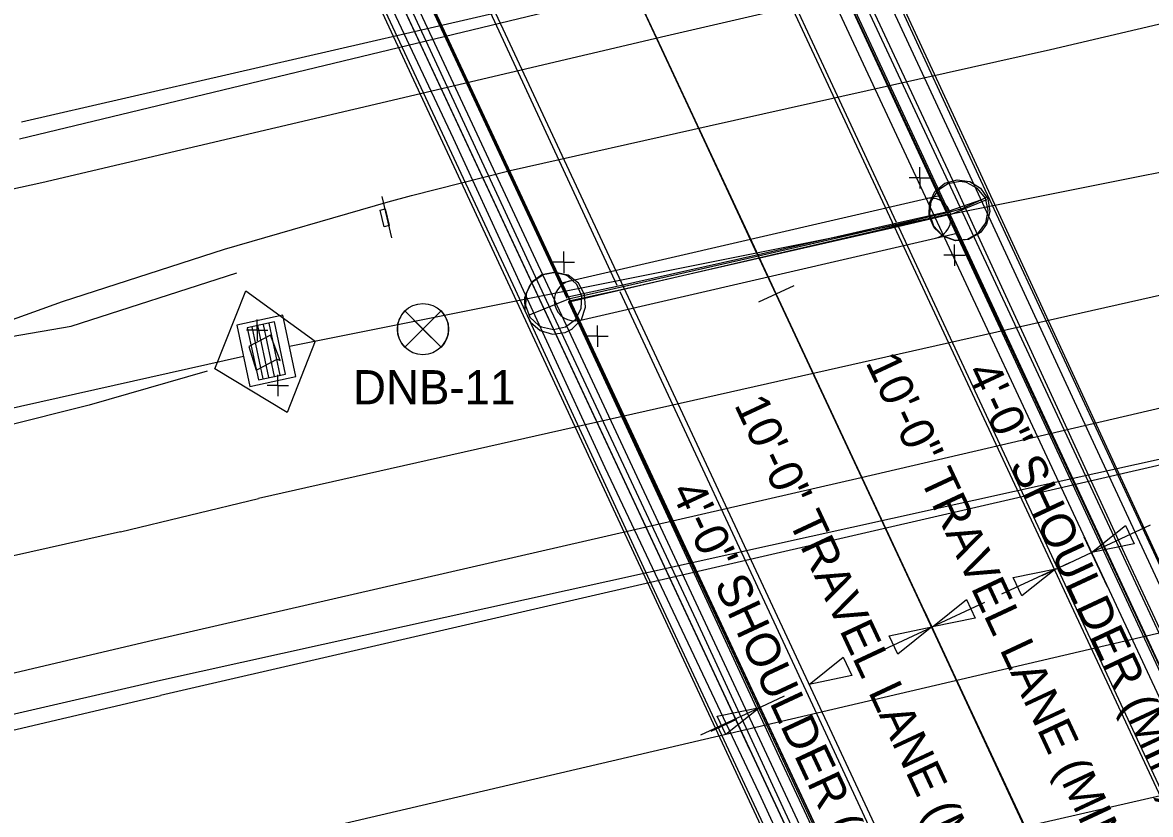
# Model space of a CAD drawing. Extents: x 1040567 to 1041254, y 1126791 to 1127594.
# Drawn here: x 1040909 to 1040992.3, y 1127132.4 to 1127190.9 of the extents above; entities that cross this region are included whole.
import ezdxf

# ---------------------------------------------------------------- set-up
doc = ezdxf.new("R2010")
doc.units = 0
for name, color, linetype in [('AC_P', 7, 'Continuous'), ('ACSRT_P', 7, 'Continuous'), ('BAJ', 7, 'Continuous'), ('BBR', 7, 'Continuous'), ('BCLBRG_P', 7, 'Continuous'), ('BDE', 7, 'Continuous'), ('BDE_P', 7, 'Continuous'), ('BDET_P', 7, 'Continuous'), ('BDSW', 7, 'Continuous'), ('BFNC', 7, 'Continuous'), ('BR', 7, 'Continuous'), ('BSE', 7, 'Continuous'), ('BSUBM', 7, 'Continuous'), ('BWI', 7, 'Continuous'), ('DCP', 7, 'Continuous'), ('DINV', 7, 'Continuous'), ('DS', 7, 'Continuous'), ('GDH', 7, 'Continuous'), ('GDH_C', 7, 'Continuous'), ('LELB', 7, 'Continuous'), ('LUKL', 7, 'Continuous'), ('O_Details_Dimensions_Extension_Lines_P', 7, 'Continuous'), ('PE', 7, 'Continuous'), ('PE_P', 7, 'Continuous'), ('PET', 7, 'Continuous'), ('PET_P', 7, 'Continuous'), ('PSU', 7, 'Continuous'), ('RBS_P', 7, 'Continuous'), ('RELB', 7, 'Continuous'), ('RGCB_P', 7, 'Continuous'), ('RGWM', 7, 'Continuous'), ('SDEL', 7, 'Continuous'), ('STBW', 7, 'Continuous'), ('STFBY', 7, 'Continuous'), ('STFBY_P', 7, 'Continuous'), ('STSEW', 7, 'Continuous'), ('STSEY', 7, 'Continuous')]:
    doc.layers.add(name, color=color, linetype=linetype)

msp = doc.modelspace()

# ---------------------------------------------------------------- linework, layer by layer
at = {"layer": 'AC_P'}
msp.add_line((1040885.873, 1127339.474), (1041008.875, 1127076.161), dxfattribs=at)
at = {"layer": 'ACSRT_P'}
msp.add_lwpolyline([(1040965.962, 1127171.427), (1040963.353, 1127170.208)], dxfattribs=at)
at = {"layer": 'BAJ'}
for points in [[(1040977.201, 1127176.865), (1040973.576, 1127176.055), (1040963.319, 1127173.7), (1040953.012, 1127171.4), (1040949.268, 1127170.586)], [(1040977.294, 1127176.639), (1040973.722, 1127175.799)], [(1040973.722, 1127175.799), (1040963.442, 1127173.467), (1040953.121, 1127171.099), (1040949.358, 1127170.29)]]:
    msp.add_lwpolyline(points, dxfattribs=at)
at = {"layer": 'BBR'}
for points in [[(1041019.719, 1127088.654), (1041004.406, 1127121.53), (1041003.585, 1127123.404), (1040990.693, 1127150.999), (1040979.268, 1127175.742), (1040977.886, 1127178.782), (1040965.491, 1127205.307), (1040953.611, 1127231.003), (1040952.138, 1127234.156), (1040937.531, 1127265.417)], [(1040989.084, 1127081.358), (1040979.685, 1127101.678), (1040973.812, 1127114.274), (1040972.939, 1127116.09), (1040958.781, 1127146.714), (1040948.043, 1127169.603), (1040947.215, 1127171.406), (1040934.066, 1127199.748), (1040923.012, 1127223.473), (1040921.387, 1127226.985), (1040913.364, 1127244.169), (1040907.222, 1127257.388)]]:
    msp.add_lwpolyline(points, dxfattribs=at)
at = {"layer": 'BCLBRG_P'}
msp.add_line((1040977.358, 1127176.709), (1040949.47, 1127170.251), dxfattribs=at)
at = {"layer": 'BDE'}
for points in [[(1040939.415, 1127265.922), (1040947.859, 1127247.808), (1040955.236, 1127232.05), (1040963.843, 1127213.367), (1040970.466, 1127199.289), (1040979.576, 1127179.6), (1040988.925, 1127159.501), (1040997.881, 1127140.234), (1041005.324, 1127124.249), (1041014.183, 1127105.141), (1041021.331, 1127089.904)], [(1040905.131, 1127257.422), (1040913.466, 1127239.609), (1040920.648, 1127224.278), (1040933.375, 1127196.889), (1040945.375, 1127171.145), (1040955.293, 1127149.679), (1040963.856, 1127131.323), (1040972.311, 1127113.367), (1040978.963, 1127098.619), (1040987.061, 1127081.333)]]:
    msp.add_lwpolyline(points, dxfattribs=at)
at = {"layer": 'BDE_P'}
msp.add_line((1040912.39, 1127244.904), (1040982.54, 1127094.731), dxfattribs=at)
at = {"layer": 'BDET_P'}
for p, q in [((1040941.284, 1127251.57), (1041011.459, 1127101.345)), ((1040914.383, 1127245.364), (1040984.534, 1127095.188))]:
    msp.add_line(p, q, dxfattribs=at)
at = {"layer": 'BDSW'}
for points in [[(1040938.228, 1127265.419), (1040936.751, 1127268.274), (1040935.099, 1127267.531), (1040944.282, 1127248.014), (1040951.626, 1127232.223), (1040953.838, 1127232.99), (1040954.435, 1127233.274), (1040954.508, 1127233.062), (1040952.645, 1127232.223), (1040951.738, 1127231.963), (1040962.689, 1127208.469), (1040977.373, 1127176.939), (1040979.827, 1127177.801), (1040980.125, 1127177.936)], [(1040951.593, 1127231.935), (1040962.526, 1127208.475), (1040977.201, 1127176.865)], [(1040923.626, 1127225.384), (1040937.857, 1127194.844), (1040949.201, 1127170.502)], [(1040949.268, 1127170.586), (1040934.086, 1127203.088), (1040923.736, 1127225.397)], [(1040980.191, 1127177.762), (1040977.506, 1127176.66), (1040987.541, 1127155.057), (1041003.054, 1127121.68), (1041005.386, 1127122.596), (1041005.717, 1127122.762)], [(1040977.294, 1127176.639), (1040987.324, 1127155.089), (1041002.898, 1127121.632)], [(1040949.328, 1127170.24), (1040964.707, 1127136.99), (1040974.918, 1127115.201)], [(1040975.07, 1127115.203), (1040960.723, 1127145.945), (1040949.358, 1127170.29)]]:
    msp.add_lwpolyline(points, dxfattribs=at)
at = {"layer": 'BFNC'}
for points in [[(1041029.028, 1127072.099), (1041018.346, 1127094.834), (1041008.209, 1127116.584), (1040997.724, 1127139.118), (1040988.217, 1127159.54), (1040977.754, 1127182.181), (1040967.557, 1127204.106), (1040957.206, 1127226.328), (1040946.955, 1127248.298), (1040937.324, 1127268.899), (1040930.675, 1127283.065)], [(1040995.864, 1127064.064), (1040985.169, 1127086.964), (1040974.401, 1127110.108), (1040963.406, 1127133.965), (1040952.032, 1127157.995), (1040940.832, 1127182.3), (1040930.319, 1127204.627), (1040919.348, 1127228.3), (1040907.363, 1127253.93), (1040897.309, 1127275.145)]]:
    msp.add_lwpolyline(points, dxfattribs=at)
at = {"layer": 'BR'}
for points in [[(1040938.828, 1127267.695), (1040955.714, 1127231.414), (1040967.747, 1127205.578), (1040979.747, 1127179.699), (1040993.173, 1127150.575), (1041022.323, 1127088.276)], [(1040904.042, 1127259.025), (1040921.201, 1127222.4), (1040933.244, 1127196.591), (1040950.275, 1127159.967), (1040963.843, 1127130.88), (1040975.411, 1127105.881), (1040987.575, 1127079.658)]]:
    msp.add_lwpolyline(points, dxfattribs=at)
at = {"layer": 'BSE'}
for p, q in [((1040948.817, 1127171.65), (1040976.713, 1127178.089)), ((1040950.115, 1127168.87), (1040978.011, 1127175.31))]:
    msp.add_line(p, q, dxfattribs=at)
for points in [[(1040978.238, 1127179.117), (1040977.325, 1127178.961), (1040976.56, 1127178.438), (1040976.082, 1127177.645), (1040975.979, 1127176.724), (1040976.269, 1127175.844), (1040976.9, 1127175.165), (1040976.981, 1127175.112), (1040977.852, 1127174.796), (1040978.775, 1127174.873), (1040979.582, 1127175.327), (1040980.127, 1127176.077), (1040980.309, 1127176.985), (1040980.096, 1127177.887), (1040979.526, 1127178.618), (1040978.704, 1127179.044), (1040978.238, 1127179.117)], [(1040949.137, 1127172.202), (1040948.249, 1127172.411), (1040947.355, 1127172.226), (1040946.623, 1127171.68), (1040946.19, 1127170.875), (1040946.138, 1127169.964), (1040946.476, 1127169.116), (1040947.141, 1127168.49), (1040947.329, 1127168.39)], [(1040947.329, 1127168.39), (1040948.22, 1127168.193), (1040949.112, 1127168.39), (1040949.836, 1127168.946), (1040950.258, 1127169.756), (1040950.298, 1127170.668), (1040949.949, 1127171.512), (1040949.276, 1127172.129), (1040949.137, 1127172.202)]]:
    msp.add_lwpolyline(points, dxfattribs=at)
for centre, start, end in [((1040976.054, 1127176.398), 282.99926, 102.99926), ((1040949.776, 1127170.336), 102.99926, 282.99926)]:
    msp.add_arc(centre, 1.5, start, end, dxfattribs=at)
at = {"layer": 'BSUBM'}
for points in [[(1040976.376, 1127178.375), (1040977.097, 1127178.988), (1040978.005, 1127179.252), (1040978.941, 1127179.121), (1040979.743, 1127178.619), (1040980.269, 1127177.833), (1040980.427, 1127176.901), (1040980.19, 1127175.985), (1040979.759, 1127175.39), (1040979.759, 1127175.39), (1040979.664, 1127175.302), (1040978.84, 1127174.838), (1040977.899, 1127174.752), (1040977.004, 1127175.059), (1040976.313, 1127175.705), (1040975.947, 1127176.576), (1040975.969, 1127177.522), (1040976.376, 1127178.375)], [(1040949.628, 1127168.261), (1040950.272, 1127168.941), (1040950.588, 1127169.837), (1040950.512, 1127170.785), (1040950.056, 1127171.62), (1040949.301, 1127172.197), (1040948.375, 1127172.417), (1040947.441, 1127172.241), (1040946.659, 1127171.7), (1040946.438, 1127171.426), (1040946.074, 1127170.547), (1040946.1, 1127169.597), (1040946.51, 1127168.739), (1040947.234, 1127168.122), (1040948.146, 1127167.854), (1040949.089, 1127167.98), (1040949.618, 1127168.25)], [(1040949.618, 1127168.25), (1040949.628, 1127168.261)]]:
    msp.add_lwpolyline(points, dxfattribs=at)
at = {"layer": 'BWI'}
for p, q in [((1040975.261, 1127179.39), (1040974.473, 1127179.39)), ((1040975.261, 1127179.39), (1040975.261, 1127180.177)), ((1040975.261, 1127179.39), (1040976.048, 1127179.39)), ((1040975.261, 1127179.39), (1040975.261, 1127178.603)), ((1040977.816, 1127173.688), (1040977.816, 1127174.476)), ((1040948.977, 1127173.175), (1040948.977, 1127173.963)), ((1040977.816, 1127173.688), (1040977.028, 1127173.688)), ((1040977.816, 1127173.688), (1040978.603, 1127173.688)), ((1040977.816, 1127173.688), (1040977.816, 1127172.901)), ((1040948.977, 1127173.175), (1040948.189, 1127173.175)), ((1040948.977, 1127173.175), (1040949.764, 1127173.175)), ((1040948.977, 1127173.175), (1040948.977, 1127172.388)), ((1040951.452, 1127167.71), (1040951.452, 1127168.498)), ((1040951.452, 1127167.71), (1040950.665, 1127167.71)), ((1040951.452, 1127167.71), (1040952.24, 1127167.71)), ((1040951.452, 1127167.71), (1040951.452, 1127166.923))]:
    msp.add_line(p, q, dxfattribs=at)
at = {"layer": 'DCP'}
for points in [[(1040928.726, 1127166.959), (1041013.434, 1127183.902)], [(1040825.333, 1127143.822), (1040925.323, 1127166.237)]]:
    msp.add_lwpolyline(points, dxfattribs=at)
at = {"layer": 'DINV'}
for p, q in [((1040926.334, 1127168.151), (1040926.334, 1127168.939)), ((1040926.334, 1127168.151), (1040925.547, 1127168.151)), ((1040926.334, 1127168.151), (1040927.121, 1127168.151)), ((1040926.334, 1127168.151), (1040926.334, 1127167.364)), ((1040927.859, 1127164.069), (1040927.859, 1127164.857)), ((1040927.859, 1127164.069), (1040927.072, 1127164.069)), ((1040927.859, 1127164.069), (1040928.647, 1127164.069)), ((1040927.859, 1127164.069), (1040927.859, 1127163.282))]:
    msp.add_line(p, q, dxfattribs=at)
at = {"layer": 'DS'}
for p, q in [((1040926.777, 1127168.575), (1040927.598, 1127164.732)), ((1040927.194, 1127168.664), (1040928.015, 1127164.821)), ((1040925.942, 1127168.397), (1040926.763, 1127164.553)), ((1040926.36, 1127168.486), (1040927.181, 1127164.642))]:
    msp.add_line(p, q, dxfattribs=at)
for points in [[(1040924.836, 1127168.518), (1040925.803, 1127163.99), (1040929.204, 1127164.717), (1040928.237, 1127169.245)], [(1040925.609, 1127168.325), (1040926.43, 1127164.482), (1040928.432, 1127164.91), (1040927.611, 1127168.753)]]:
    msp.add_lwpolyline(points, close=True, dxfattribs=at)
at = {"layer": 'GDH'}
for p, q in [((1040937.244, 1127169.564), (1040939.917, 1127166.891)), ((1040939.917, 1127169.564), (1040937.244, 1127166.891))]:
    msp.add_line(p, q, dxfattribs=at)
for points in [[(1040937.244, 1127166.891), (1040938.58, 1127168.228), (1040937.244, 1127169.564)], [(1040939.917, 1127169.564), (1040938.58, 1127168.228), (1040939.917, 1127166.891)]]:
    msp.add_lwpolyline(points, dxfattribs=at)
msp.add_circle((1040938.58, 1127168.228), 1.89, dxfattribs=at)
for start, end in [(135, 180), (360, 45), (180, 225), (315, 0)]:
    msp.add_arc((1040938.58, 1127168.228), 1.89, start, end, dxfattribs=at)
at = {"layer": 'LELB'}
msp.add_lwpolyline([(1040925.719, 1127166.953), (1040926.265, 1127165.193), (1040927.812, 1127165.998), (1040928.04, 1127165.914), (1040927.331, 1127167.785), (1040925.719, 1127166.953)], dxfattribs=at)
at = {"layer": 'LUKL'}
msp.add_lwpolyline([(1040980.139, 1127177.917), (1040978.354, 1127177.095), (1040977.305, 1127176.801), (1040963.353, 1127173.608), (1040949.319, 1127170.426), (1040946.586, 1127169.341), (1040946.426, 1127169.264)], dxfattribs=at)
at = {"layer": 'O_Details_Dimensions_Extension_Lines_P'}
for p, q in [((1040992.269, 1127153.765), (1040987.921, 1127151.734)), ((1040989.101, 1127149.207), (1040987.391, 1127152.867)), ((1040985.892, 1127150.786), (1040987.921, 1127151.734)), ((1040981.314, 1127148.679), (1040985.296, 1127150.539)), ((1040984.299, 1127150.042), (1040986.339, 1127150.995)), ((1040976.152, 1127146.236), (1040980.062, 1127148.063)), ((1040977.425, 1127143.511), (1040975.623, 1127147.369)), ((1040972.225, 1127144.402), (1040976.184, 1127146.251)), ((1040963.119, 1127140.148), (1040965.28, 1127141.157)), ((1040959.091, 1127138.267), (1040963.44, 1127140.298)), ((1040962.718, 1127137.165), (1040961.086, 1127140.658)), ((1040959.857, 1127138.545), (1040961.758, 1127139.433))]:
    msp.add_line(p, q, dxfattribs=at)
for points in [[(1040991.07, 1127152.377), (1040987.921, 1127151.734), (1040990.435, 1127153.737)], [(1040982.147, 1127149.896), (1040985.296, 1127150.539), (1040982.782, 1127148.536)], [(1040979.334, 1127146.895), (1040976.184, 1127146.251), (1040978.699, 1127148.254)], [(1040973.002, 1127145.593), (1040976.152, 1127146.236), (1040973.637, 1127144.233)], [(1040970.232, 1127142.643), (1040967.082, 1127141.999), (1040969.597, 1127144.002)], [(1040960.291, 1127139.655), (1040963.44, 1127140.298), (1040960.926, 1127138.296)]]:
    msp.add_lwpolyline(points, close=True, dxfattribs=at)
at = {"layer": 'PE'}
for points in [[(1040956.515, 1127189.886), (1040990.943, 1127197.845)], [(1040910.451, 1127179.049), (1040956.515, 1127189.886)], [(1040821.708, 1127159.344), (1040864.776, 1127169.055), (1040910.451, 1127179.049)], [(1041005.278, 1127165.233), (1040970.926, 1127157.248)], [(1040970.926, 1127157.248), (1040918.312, 1127145.164)], [(1040918.312, 1127145.164), (1040872.548, 1127134.381), (1040830.157, 1127124.61)]]:
    msp.add_lwpolyline(points, dxfattribs=at)
at = {"layer": 'PE_P'}
for points in [[(1040916.887, 1127306.161), (1041021.781, 1127081.611), (1041023.896, 1127077.084), (1041026.013, 1127072.558), (1041028.13, 1127068.033), (1041030.249, 1127063.508), (1041032.369, 1127058.983), (1041034.49, 1127054.459), (1041036.612, 1127049.936), (1041037.879, 1127047.236)], [(1040891.518, 1127294.31), (1040996.412, 1127069.76), (1040998.531, 1127065.227), (1041000.65, 1127060.695), (1041002.771, 1127056.163), (1041004.893, 1127051.631), (1041007.015, 1127047.1), (1041009.139, 1127042.57), (1041009.957, 1127040.827)]]:
    msp.add_lwpolyline(points, dxfattribs=at)
at = {"layer": 'PET'}
for points in [[(1040908.8, 1127182.265), (1040989.254, 1127201.677)], [(1041006.271, 1127161.562), (1040919.195, 1127142.278)], [(1040919.195, 1127142.278), (1040873.828, 1127131.824), (1040831.003, 1127121.94)]]:
    msp.add_lwpolyline(points, dxfattribs=at)
at = {"layer": 'PET_P'}
for points in [[(1040894.933, 1127343.706), (1041018.157, 1127079.918), (1041020.272, 1127075.391), (1041022.389, 1127070.864), (1041024.507, 1127066.337), (1041026.627, 1127061.811), (1041028.747, 1127057.286), (1041030.868, 1127052.761), (1041032.991, 1127048.237), (1041035.115, 1127043.713)], [(1040876.813, 1127335.242), (1041000.036, 1127071.453), (1041002.154, 1127066.921), (1041004.273, 1127062.389), (1041006.394, 1127057.858), (1041008.515, 1127053.328), (1041010.637, 1127048.798), (1041012.761, 1127044.269)]]:
    msp.add_lwpolyline(points, dxfattribs=at)
at = {"layer": 'PSU'}
msp.add_lwpolyline([(1040824.158, 1127151.223), (1040866.581, 1127160.511), (1040912.599, 1127168.454), (1040924.84, 1127172.38)], dxfattribs=at)
at = {"layer": 'RBS_P'}
for points in [[(1040917.793, 1127306.584), (1041022.687, 1127082.034), (1041024.802, 1127077.508), (1041026.919, 1127072.982), (1041029.036, 1127068.456), (1041031.155, 1127063.931), (1041033.275, 1127059.407), (1041035.396, 1127054.883), (1041037.518, 1127050.359), (1041038.785, 1127047.66)], [(1040889.729, 1127293.414), (1040994.601, 1127068.913), (1040996.719, 1127064.38), (1040998.839, 1127059.847), (1041000.959, 1127055.315), (1041003.081, 1127050.783), (1041005.204, 1127046.252), (1041007.329, 1127041.721), (1041008.147, 1127039.977)]]:
    msp.add_lwpolyline(points, dxfattribs=at)
at = {"layer": 'RELB'}
for points in [[(1040923.219, 1127165.306), (1040925.494, 1127171.052), (1040930.626, 1127167.33), (1040928.562, 1127162.068), (1040923.219, 1127165.306)], [(1040922.65, 1127165.112), (1040913.937, 1127162.623), (1040869.211, 1127151.4), (1040826.591, 1127140.439)]]:
    msp.add_lwpolyline(points, dxfattribs=at)
at = {"layer": 'RGCB_P'}
for p, q in [((1040942.28, 1127251.8), (1041012.456, 1127101.573)), ((1040913.386, 1127245.134), (1040983.609, 1127094.742))]:
    msp.add_line(p, q, dxfattribs=at)
at = {"layer": 'RGWM'}
for points in [[(1040888.432, 1127161.373), (1040900.126, 1127166.003), (1040911.962, 1127170.26), (1040923.927, 1127174.137), (1040936.009, 1127177.633), (1040937.727, 1127178.096), (1040945.023, 1127179.944), (1040959.716, 1127183.235), (1040984.897, 1127188.856), (1040995.3, 1127191.31), (1041016.049, 1127196.462)], [(1041051.905, 1127186.103), (1041027.584, 1127179.409), (1041003.161, 1127173.101), (1040999.611, 1127172.219), (1040926.446, 1127155.714)], [(1040916.256, 1127153.249), (1040926.446, 1127155.714)], [(1040916.256, 1127153.249), (1040871.027, 1127143.112), (1040827.707, 1127134.902)]]:
    msp.add_lwpolyline(points, dxfattribs=at)
at = {"layer": 'SDEL'}
msp.add_line((1040936.294, 1127174.955), (1040935.57, 1127178.02), dxfattribs=at)
msp.add_lwpolyline([(1040935.786, 1127177.105), (1040936.078, 1127175.869), (1040935.707, 1127175.782), (1040935.415, 1127177.018)], close=True, dxfattribs=at)
at = {"layer": 'STBW'}
msp.add_lwpolyline([(1041007.885, 1127149.284), (1040929.784, 1127131.005)], dxfattribs=at)
at = {"layer": 'STFBY'}
for points in [[(1040963.268, 1127173.717), (1040950.169, 1127201.941), (1040937.747, 1127228.54)], [(1040988.982, 1127118.575), (1040976.759, 1127144.874), (1040963.429, 1127173.402)]]:
    msp.add_lwpolyline(points, dxfattribs=at)
at = {"layer": 'STFBY_P'}
msp.add_lwpolyline([(1040954.077, 1127193.468), (1040956.193, 1127188.938), (1040958.309, 1127184.408), (1040960.425, 1127179.878), (1040962.541, 1127175.348), (1040964.657, 1127170.818), (1040966.773, 1127166.288), (1040968.89, 1127161.758), (1040971.006, 1127157.227), (1040973.122, 1127152.697), (1040975.238, 1127148.167), (1040977.354, 1127143.637), (1040979.47, 1127139.107), (1040981.587, 1127134.577), (1040983.703, 1127130.047), (1040985.819, 1127125.517), (1040987.935, 1127120.987), (1040990.051, 1127116.457), (1040992.167, 1127111.926), (1040994.284, 1127107.396), (1040996.4, 1127102.866), (1040998.516, 1127098.336), (1041000.632, 1127093.806)], dxfattribs=at)
at = {"layer": 'STSEW'}
for points in [[(1040973.544, 1127176.095), (1040959.771, 1127205.651), (1040947.896, 1127230.933)], [(1040952.919, 1127171.435), (1040940.716, 1127197.775), (1040927.348, 1127226.167)], [(1040999.299, 1127120.859), (1040986.64, 1127147.948), (1040973.701, 1127175.758)], [(1040978.659, 1127116.127), (1040967.041, 1127141.164), (1040953.148, 1127170.99)], [(1041014.056, 1127138.583), (1040983.259, 1127131.542)]]:
    msp.add_lwpolyline(points, dxfattribs=at)
at = {"layer": 'STSEY'}
for points in [[(1040908.934, 1127183.539), (1040955.148, 1127194.178)], [(1041006.434, 1127161.275), (1040972.555, 1127153.492)], [(1040972.555, 1127153.492), (1040919.199, 1127141.177)], [(1040831.753, 1127120.926), (1040874.026, 1127130.579), (1040919.199, 1127141.177)]]:
    msp.add_lwpolyline(points, dxfattribs=at)

# ---------------------------------------------------------------- texts
at = {"layer": 'GDH_C'}
msp.add_text('DNB-11', height=2.5197, rotation=360, dxfattribs=at).set_placement((1040933.42, 1127162.678))
at = {"layer": 'O_Details_Dimensions_Extension_Lines_P'}
for s, p in [('10\'-0" TRAVEL LANE (MIN)', (1040971.221, 1127165.783)), ('4\'-0" SHOULDER (MIN)', (1040978.628, 1127165.089)), ('10\'-0" TRAVEL LANE (MIN)', (1040961.524, 1127162.647)), ('4\'-0" SHOULDER (MIN)', (1040956.835, 1127156.289))]:
    msp.add_text(s, height=2.5008, rotation=295.03874, dxfattribs=at).set_placement(p)

doc.saveas('drawing.dxf')
